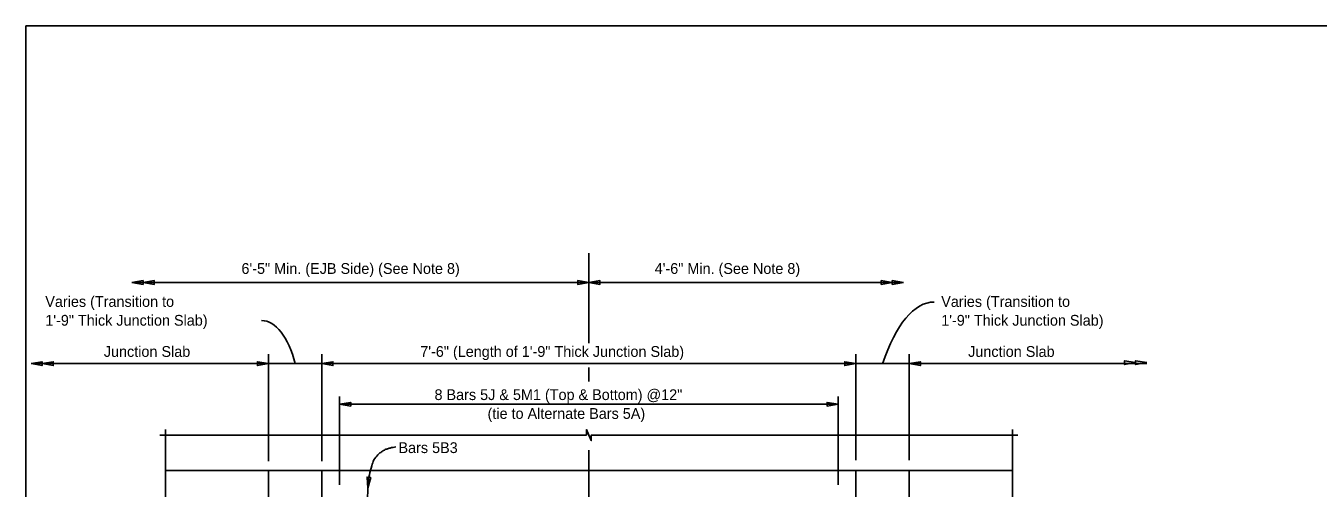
# Model space of a CAD drawing. Extents: x 0 to 54.1, y -0.5 to 22.5.
# Drawn here: x 0.01 to 18.16, y 14.51 to 21 of the extents above; entities that cross this region are included whole.
import ezdxf

# ---------------------------------------------------------------- set-up
doc = ezdxf.new("R2010")
doc.units = 0
for name, color, linetype in [('ActivePts-ConstElements', 7, 'Continuous'), ('CL_Major', 7, 'Continuous'), ('Dimension', 7, 'Continuous'), ('TextStructures', 7, 'Continuous'), ('WallConc', 7, 'Continuous'), ('WallConc_h', 7, 'Continuous')]:
    doc.layers.add(name, color=color, linetype=linetype)

msp = doc.modelspace()

# ---------------------------------------------------------------- linework, layer by layer
at = {"layer": 'ActivePts-ConstElements'}
msp.add_lwpolyline([(0.012, 1.54), (30.8, 1.54), (30.8, 21), (0.012, 21)], close=True, dxfattribs=at)
at = {"layer": 'CL_Major'}
for p, q in [((7.919, 17.807), (7.919, 16.544)), ((7.919, 16.203), (7.919, 16.007)), ((7.919, 15.044), (7.919, 5.002))]:
    msp.add_line(p, q, dxfattribs=at)
at = {"layer": 'Dimension'}
for p, q in [((1.502, 17.398), (7.919, 17.398)), ((7.919, 17.398), (12.336, 17.398)), ((3.419, 16.391), (3.419, 14.891)), ((4.169, 16.391), (4.169, 14.891)), ((11.669, 16.391), (11.669, 14.905)), ((12.419, 16.391), (12.419, 14.905)), ((0.085, 16.258), (3.419, 16.258)), ((4.169, 16.258), (3.419, 16.258)), ((4.169, 16.258), (11.669, 16.258)), ((11.669, 16.258), (12.419, 16.258)), ((12.419, 16.258), (15.753, 16.258)), ((4.419, 15.798), (4.419, 14.555)), ((11.419, 15.798), (11.419, 14.555)), ((4.419, 15.689), (11.419, 15.689))]:
    msp.add_line(p, q, dxfattribs=at)
for points in [[(1.502, 17.398), (1.659, 17.371), (1.659, 17.424)], [(1.659, 17.398), (1.815, 17.371), (1.815, 17.424)], [(7.919, 17.398), (7.763, 17.371), (7.763, 17.424)], [(7.919, 17.398), (8.075, 17.371), (8.075, 17.424)], [(12.18, 17.398), (12.024, 17.424), (12.024, 17.371)], [(12.336, 17.398), (12.18, 17.424), (12.18, 17.371)], [(0.085, 16.258), (0.241, 16.231), (0.241, 16.284)], [(0.241, 16.258), (0.397, 16.231), (0.397, 16.284)], [(3.419, 16.258), (3.263, 16.284), (3.263, 16.231)], [(4.169, 16.258), (4.325, 16.231), (4.325, 16.284)], [(11.669, 16.258), (11.513, 16.284), (11.513, 16.231)], [(12.419, 16.258), (12.575, 16.231), (12.575, 16.284)], [(15.597, 16.272), (15.441, 16.299), (15.441, 16.246)], [(15.753, 16.272), (15.597, 16.299), (15.597, 16.246)], [(4.419, 15.689), (4.575, 15.662), (4.575, 15.715)], [(11.419, 15.689), (11.263, 15.715), (11.263, 15.662)], [(4.816, 14.508), (4.856, 14.661), (4.803, 14.665)]]:
    msp.add_lwpolyline(points, close=True, dxfattribs=at)
for points in [[(1.893, 15.256), (7.885, 15.256), (7.885, 15.333), (7.919, 15.256), (7.953, 15.178), (7.953, 15.256), (13.945, 15.256)], [(1.971, 12.257), (1.971, 13.202), (1.893, 13.202), (1.971, 13.236), (2.048, 13.27), (1.971, 13.27), (1.971, 15.333)], [(13.867, 8.647), (13.867, 13.202), (13.79, 13.202), (13.867, 13.236), (13.945, 13.27), (13.867, 13.27), (13.867, 15.333)]]:
    msp.add_lwpolyline(points, dxfattribs=at)
for centre, major_axis, ratio, start_param, end_param in [((12.749, 14.616), (-0.017, -2.507), 0.37692, 3.141586, 4.001141), ((3.336, 15.756), (0.013, -1.107), 0.468554, 2.035982, 3.141597)]:
    msp.add_ellipse(centre, major_axis=major_axis, ratio=ratio, start_param=start_param, end_param=end_param, dxfattribs=at)
msp.add_spline([(5.21, 15.091), (5.128, 15.074), (5.081, 15.06), (5.037, 15.04), (4.995, 15.012), (4.956, 14.978), (4.901, 14.906), (4.869, 14.825), (4.819, 14.564), (4.812, 14.406), (4.804, 14.249), (4.796, 13.934), (4.768, 9.508)], degree=3, dxfattribs=at)
at = {"layer": 'WallConc'}
msp.add_line((13.867, 14.758), (1.971, 14.758), dxfattribs=at)
at = {"layer": 'WallConc_h'}
for p, q in [((3.419, 9.299), (3.419, 14.758)), ((4.169, 9.299), (4.169, 14.758)), ((11.669, 9.299), (11.669, 14.758)), ((12.419, 11.801), (12.419, 14.758))]:
    msp.add_line(p, q, dxfattribs=at)

# ---------------------------------------------------------------- texts
at = {"layer": 'Dimension'}
for s, p in [('Varies (Transition to', (0.285, 17.055)), ('Varies (Transition to', (12.867, 17.055)), ('1\'-9" Thick Junction Slab)', (0.285, 16.791)), ('1\'-9" Thick Junction Slab)', (12.867, 16.791))]:
    msp.add_text(s, height=0.1512, dxfattribs=at).set_placement(p)
at = {"layer": 'TextStructures'}
for s, p in [('6\'-5" Min. (EJB Side) (See Note 8)', (3.04, 17.518)), ('4\'-6" Min. (See Note 8)', (8.843, 17.518)), ('Junction Slab', (1.107, 16.353)), ('7\'-6" (Length of 1\'-9" Thick Junction Slab)', (5.551, 16.353)), ('Junction Slab', (13.245, 16.353)), ('8 Bars 5J & 5M1 (Top & Bottom) @12"', (5.751, 15.747)), ('(tie to Alternate Bars 5A)', (6.496, 15.483)), ('Bars 5B3', (5.245, 15.003))]:
    msp.add_text(s, height=0.1512, dxfattribs=at).set_placement(p)

doc.saveas('drawing.dxf')
